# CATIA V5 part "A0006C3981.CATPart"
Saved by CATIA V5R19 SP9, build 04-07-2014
Part number: A0006C3981
Bounding box of the stored display mesh (mm): x 0 to 100, y -40 to 40, z 0 to 40
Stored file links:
  O:\Catia Forum\A0006C3981.CATPart
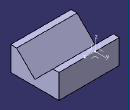
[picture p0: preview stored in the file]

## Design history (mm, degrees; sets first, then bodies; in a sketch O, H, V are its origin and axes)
AxisSystem1: origin (0, 0, 0), X (1, 0, 0), Y (0, 1, 0), Z (0, 0, 1)
Body1 (main body)
  Sketch1 on YZ plane of AxisSystem1, origin (0, 0, 0), H (0, 1, 0), V (0, 0, 1)
    point P1 (-40, 0)
    line L1 (-40, 0) -> (-40, 40)
    line L2 (-40, 40) -> (-30, 40)
    point P3 (-30, 40)
    line L3 (-30, 40) -> (0, 10)
    point P4 (0, 10)
    line L4 (0, 10) -> (30, 40)
    point P5 (30, 40)
    line L5 (30, 40) -> (40, 40)
    line L6 (40, 40) -> (40, 0)
    point P7 (40, 0)
    line L7 (40, 0) -> (-40, 0)
    angle V L3 = 135
    distance L1 L6 = 80
    distance P3 P5 = 60
    distance L5 L7 = 40
    coincidence: P1 H, P4 V, P7 H, L5 L2
    vertical: L1 V, L6 V
    horizontal: L2 H, L5 H, L7 H
    perpendicularity: L3 L4
    symmetry: L6 L1 V
  Pad1: profile Sketch1, direction (1, 0, 0), length 100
